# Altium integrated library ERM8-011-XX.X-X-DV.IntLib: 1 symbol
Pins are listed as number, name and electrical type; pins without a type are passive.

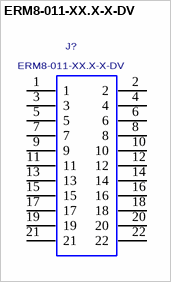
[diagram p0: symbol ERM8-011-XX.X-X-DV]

## ERM8-011-XX.X-X-DV
designator J?
0.8mm Edge Rate Terminal Assembly, Double Vertical Row, 22 Pins.; MANUFACTURER: SAMTEC
footprint ERM8-011-XX.X-X-DV
pins: 1, 2, 3, 4, 5, 6, 7, 8, 9, 10, 11, 12, 13, 14, 15, 16, 17, 18, 19, 20, 21, 22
